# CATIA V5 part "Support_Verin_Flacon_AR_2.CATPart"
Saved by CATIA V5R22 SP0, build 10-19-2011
Part number: Support_Verin_Flacon_AR_2
Bounding box of the stored display mesh (mm): x 0 to 9, y -28.5 to 28.5, z -20 to 18.5
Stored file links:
  D:\PER\CAO_PER_MODIF_2025\CAO_PER_pick&place_2024P\Sous_Ensemble_Flacon\Support_Verin_Flacon_AR_2.CATPart
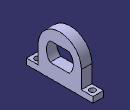
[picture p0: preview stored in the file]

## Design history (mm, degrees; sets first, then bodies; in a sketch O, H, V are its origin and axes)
Body1 (main body)
  Sketch1 on yz-plane, origin (0, 0, 0), H (0, 1, 0), V (0, 0, 1)
    arc A1 centre (0, 0) radius 11.5 from (8.2614, -8) to (8.2614, 8) ccw
    point P1 (-8.2614, 8)
    line L1 (-8.2614, 8) -> (8.2614, 8)
    line L2 (8.2614, -8) -> (-8.2614, -8)
    arc A2 centre (0, 0) radius 11.5 from (-8.2614, 8) to (-8.2614, -8) ccw
    arc A3 centre (0, 0) radius 18.5 from (18.5, 0) to (-18.5, 0) ccw
    point P5 (18.5, -20)
    line L3 (18.5, -20) -> (-18.5, -20)
    line L4 (-18.5, -15) -> (-18.5, 0)
    line L5 (18.5, 0) -> (18.5, -15)
    point P6 (-18.5, -20)
    point P7 (-18.5, 0)
    line L6 (-18.5, -20) -> (-28.5, -20)
    line L7 (-28.5, -20) -> (-28.5, -15)
    line L8 (-28.5, -15) -> (-18.5, -15)
    point P9 (-28.5, -20)
    point P10 (-28.5, -15)
    point P11 (-18.5, -15)
    point P12 (18.5, -20)
    point P13 (28.5, -20)
    point P14 (28.5, -15)
    point P15 (18.5, -15)
    line L9 (18.5, -20) -> (28.5, -20)
    line L10 (28.5, -20) -> (28.5, -15)
    line L11 (28.5, -15) -> (18.5, -15)
    radius A1 = 11.5
    distance O L2 = 8
    distance A3 A1 = 7
    distance H L3 = 20
    length L7 = 5
    length L8 = 10
    horizontal: L1 H, L2 H, L3 H, L6 H, L8 H
    equidistance: L2 L1 O
    coincidence: P1 A1, A1 A2, P7 H, P6 L4, P5 L5, P5 P12
    vertical: L4 V, L5 V, L7 V
    tangency: L5 A3
    symmetry: P6 P12 V, P9 P13 V, P10 P14 V, P11 P15 V, L6 L9 V, L7 L10 V, L8 L11 V
  Pad1: profile Sketch1, direction (1, 0, 0), length 9
  Sketch2 on face of Pad1 from Sketch1.L8, origin (4.0945, -21.7064, -15), H (1, 0, 0), V (0, 1, 0)
    point P1 (0.4055, -1.7936)
    reference projected point E1 (-4.0945, -6.7936) from vertex [face of Pad1 from Sketch1.L7 | start face of Pad1 | face of Pad1 from Sketch1.L8]
    reference projected point E2 (4.9055, 3.2064) from vertex [face of Pad1 from Sketch1.L4 | end face of Pad1 | face of Pad1 from Sketch1.A3]
    reference projected point E3 (4.9055, -6.7936) from vertex [face of Pad1 from Sketch1.L7 | end face of Pad1 | face of Pad1 from Sketch1.L8]
    reference projected point E4 (-4.0945, 3.2064) from vertex [face of Pad1 from Sketch1.L4 | start face of Pad1 | face of Pad1 from Sketch1.A3]
    equidistance: E1 E2 P1, E3 E4 P1
  Hole1: placed by Sketch2, at (4.5, -23.5, -15) direction (0, 0, -1), diameter 5, through (limit type 6)
  Mirror1: of Hole1, about zx-plane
